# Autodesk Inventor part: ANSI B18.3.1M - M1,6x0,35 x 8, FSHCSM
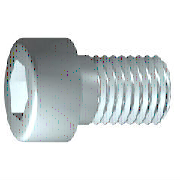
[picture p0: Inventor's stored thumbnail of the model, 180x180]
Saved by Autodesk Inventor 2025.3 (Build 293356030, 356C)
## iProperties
Created: 2024-01
Part Number: ANSI B18.3.1M - M1,6x0,35 x 8, FSHCSM
Material: Acciaio, Dolce
Description: Vite forgiata a testa incassata - Metrico
Document SubType Name: Modeling
Standard: ANSI B18.3.1M
Designer: R5800u
Standard Revision: 1979
Standards Organization: ANSI
Language: it-IT
Size Designation: M1,6x0,35 x 8
Categories: <MemberInstance><Categories><Category DisplayName="Elementi di fissaggio" InternalName="e4da775c-781d-43d5-af7c-5136215cf5a6" Mnemonic="FSTN"><Category DisplayN
Density: 7.85 g/cm^3
Appearance: Semilucidato
IsCustomPart: 0
Author: R5800u
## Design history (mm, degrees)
body "Solid1"
workplane "Work Plane1"
fillet "Fillet2" dims "d30" = 0.1 (= R)
revolve "Corpo" stored, may be unused: angle "d10" = 90 deg
sketch "Schizzo2"
  geometry: L1 (0, -2.1)-(0, 2.1) reference; L2 (-2.1, 0)-(2.1, 0) reference; L3 (0.866, 0)-(0.433, -0.75); L4 (0.433, -0.75)-(-0.433, -0.75); L5 (-0.433, -0.75)-(-0.866, 0); L6 (-0.866, 0)-(-0.433, 0.75); L7 (-0.433, 0.75)-(0.433, 0.75); L8 (0.433, 0.75)-(0.866, 0); 2 further points
  constraints: 12 end point, 1 coincident, 1 horizontal alignment, 1 point on line, 12 other
extrude "Intaglio" join sketch "Schizzo2" stored distance "d11" = 10; taper "d12" = 0 deg
fillet "Raccordo1" dims "d17" = 0.16 (= RR)
feature "Filettatura" dims "d13" = 7.08529 (= GEL), "d14" = 0
chamfer "Smusso1" distance "d15" = 0.21471 (= -0.5 x SPD + 0.5 x GD); stored, may be unused: second distance "d16" = 0.21471 (= GUL), angle "d27" = 45 deg
sketch "Schizzo1"
  geometry: L1 (-0.3, 0)-(8, 0); L2 (8, 0)-(8, 0.8); L3 (8, 0.8)-(0.915, 0.8); L4 (0.915, 0.8)-(0.7, 0.8); L5 (0.7, 0.8)-(0, 0.8); L6 (0, 0.8)-(0, 1.5); L7 (0, 1.5)-(-1.6, 1.5); L8 (-1.6, 1.5)-(-1.6, 0.866); L9 (-1.6, 0.866)-(-0.8, 0.866); L10 (-0.8, 0.866)-(-0.3, 0); L11 (-3.52, 0)-(9.92, 0) reference; L12 (0, -0.3)-(0, 1.8) reference; L13 (0.915, 0.8)-(0, 0.8)
  constraints: 22 end point, 6 parallel, 2 collinear, 2 perpendicular, 1 horizontal, 1 point on line
  dimensions: "d1" = 7.08529 distance from line of L3.end L2 (= GEL); "d2" = 0.21481 distance of L4.end L3.end (computed from GAL); "d3" = 1.6 distance between parallel lines of L8 L6 (= KOH); "d4" = 0.8 distance of L8.end L9.end (= INTI); "d5" = 60 deg angle of L10 L1; "d6" = 1.6 diameter of L3 L1 (= GD); "d7" = 1.6 diameter of L5 L1 (= BDM); "d8" = 1.73205 diameter of L9 L1 (= 1.1547 x SW); "d9" = 3 diameter of L7 L1 (= KOD); "d26" = 8 distance between parallel lines of L12 L2 (= NLG)
other parameters: "GD" = 1.6 (= NND) [user parameter; used in 2 equation terms], "NLG" = 8 [user parameter; used in 1 equation term], "GEL" = 7.08529 [user parameter; used in 2 equation terms], "KOD" = 3 [user parameter; used in 1 equation term], "KOH" = 1.6 [user parameter; used in 1 equation term], "INTI" = 0.8 [user parameter; used in 1 equation term], "GAL" = 0.21471 (= 0.61345 x PTC) [user parameter; used in 1 equation term], "GUL" = 0.21471 (= 0.61345 x PTC) [user parameter; used in 1 equation term], "BDM" = 1.6 (= NND) [user parameter; used in 1 equation term], "SW" = 1.5 [user parameter; used in 2 equation terms], "RR" = 0.16 [user parameter; used in 1 equation term], "SPD" = 1.17058 [user parameter; used in 1 equation term], "d19" = 0, "d28" = 0, "d29" = 0, "R" = 0.1 [user parameter; used in 1 equation term], "TOA" = 30 deg [user parameter], "THREADDIA" = 1.6 [user parameter; used in 1 equation term], "TPU" = 28.57143 (computed from PTC) [user parameter], "PTC" = 0.35 [user parameter; used in 4 equation terms], "NND" = 1.6 [user parameter; used in 2 equation terms], "E0" = 1.7325 (= 1.155 x SW) [user parameter], "GD1" = 1.17059 (= THREADDIA - 1.2269 x PTC) [user parameter]
